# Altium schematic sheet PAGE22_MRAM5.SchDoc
size 381 x 381 mm; SheetNumber: 23; SheetTotal: 28
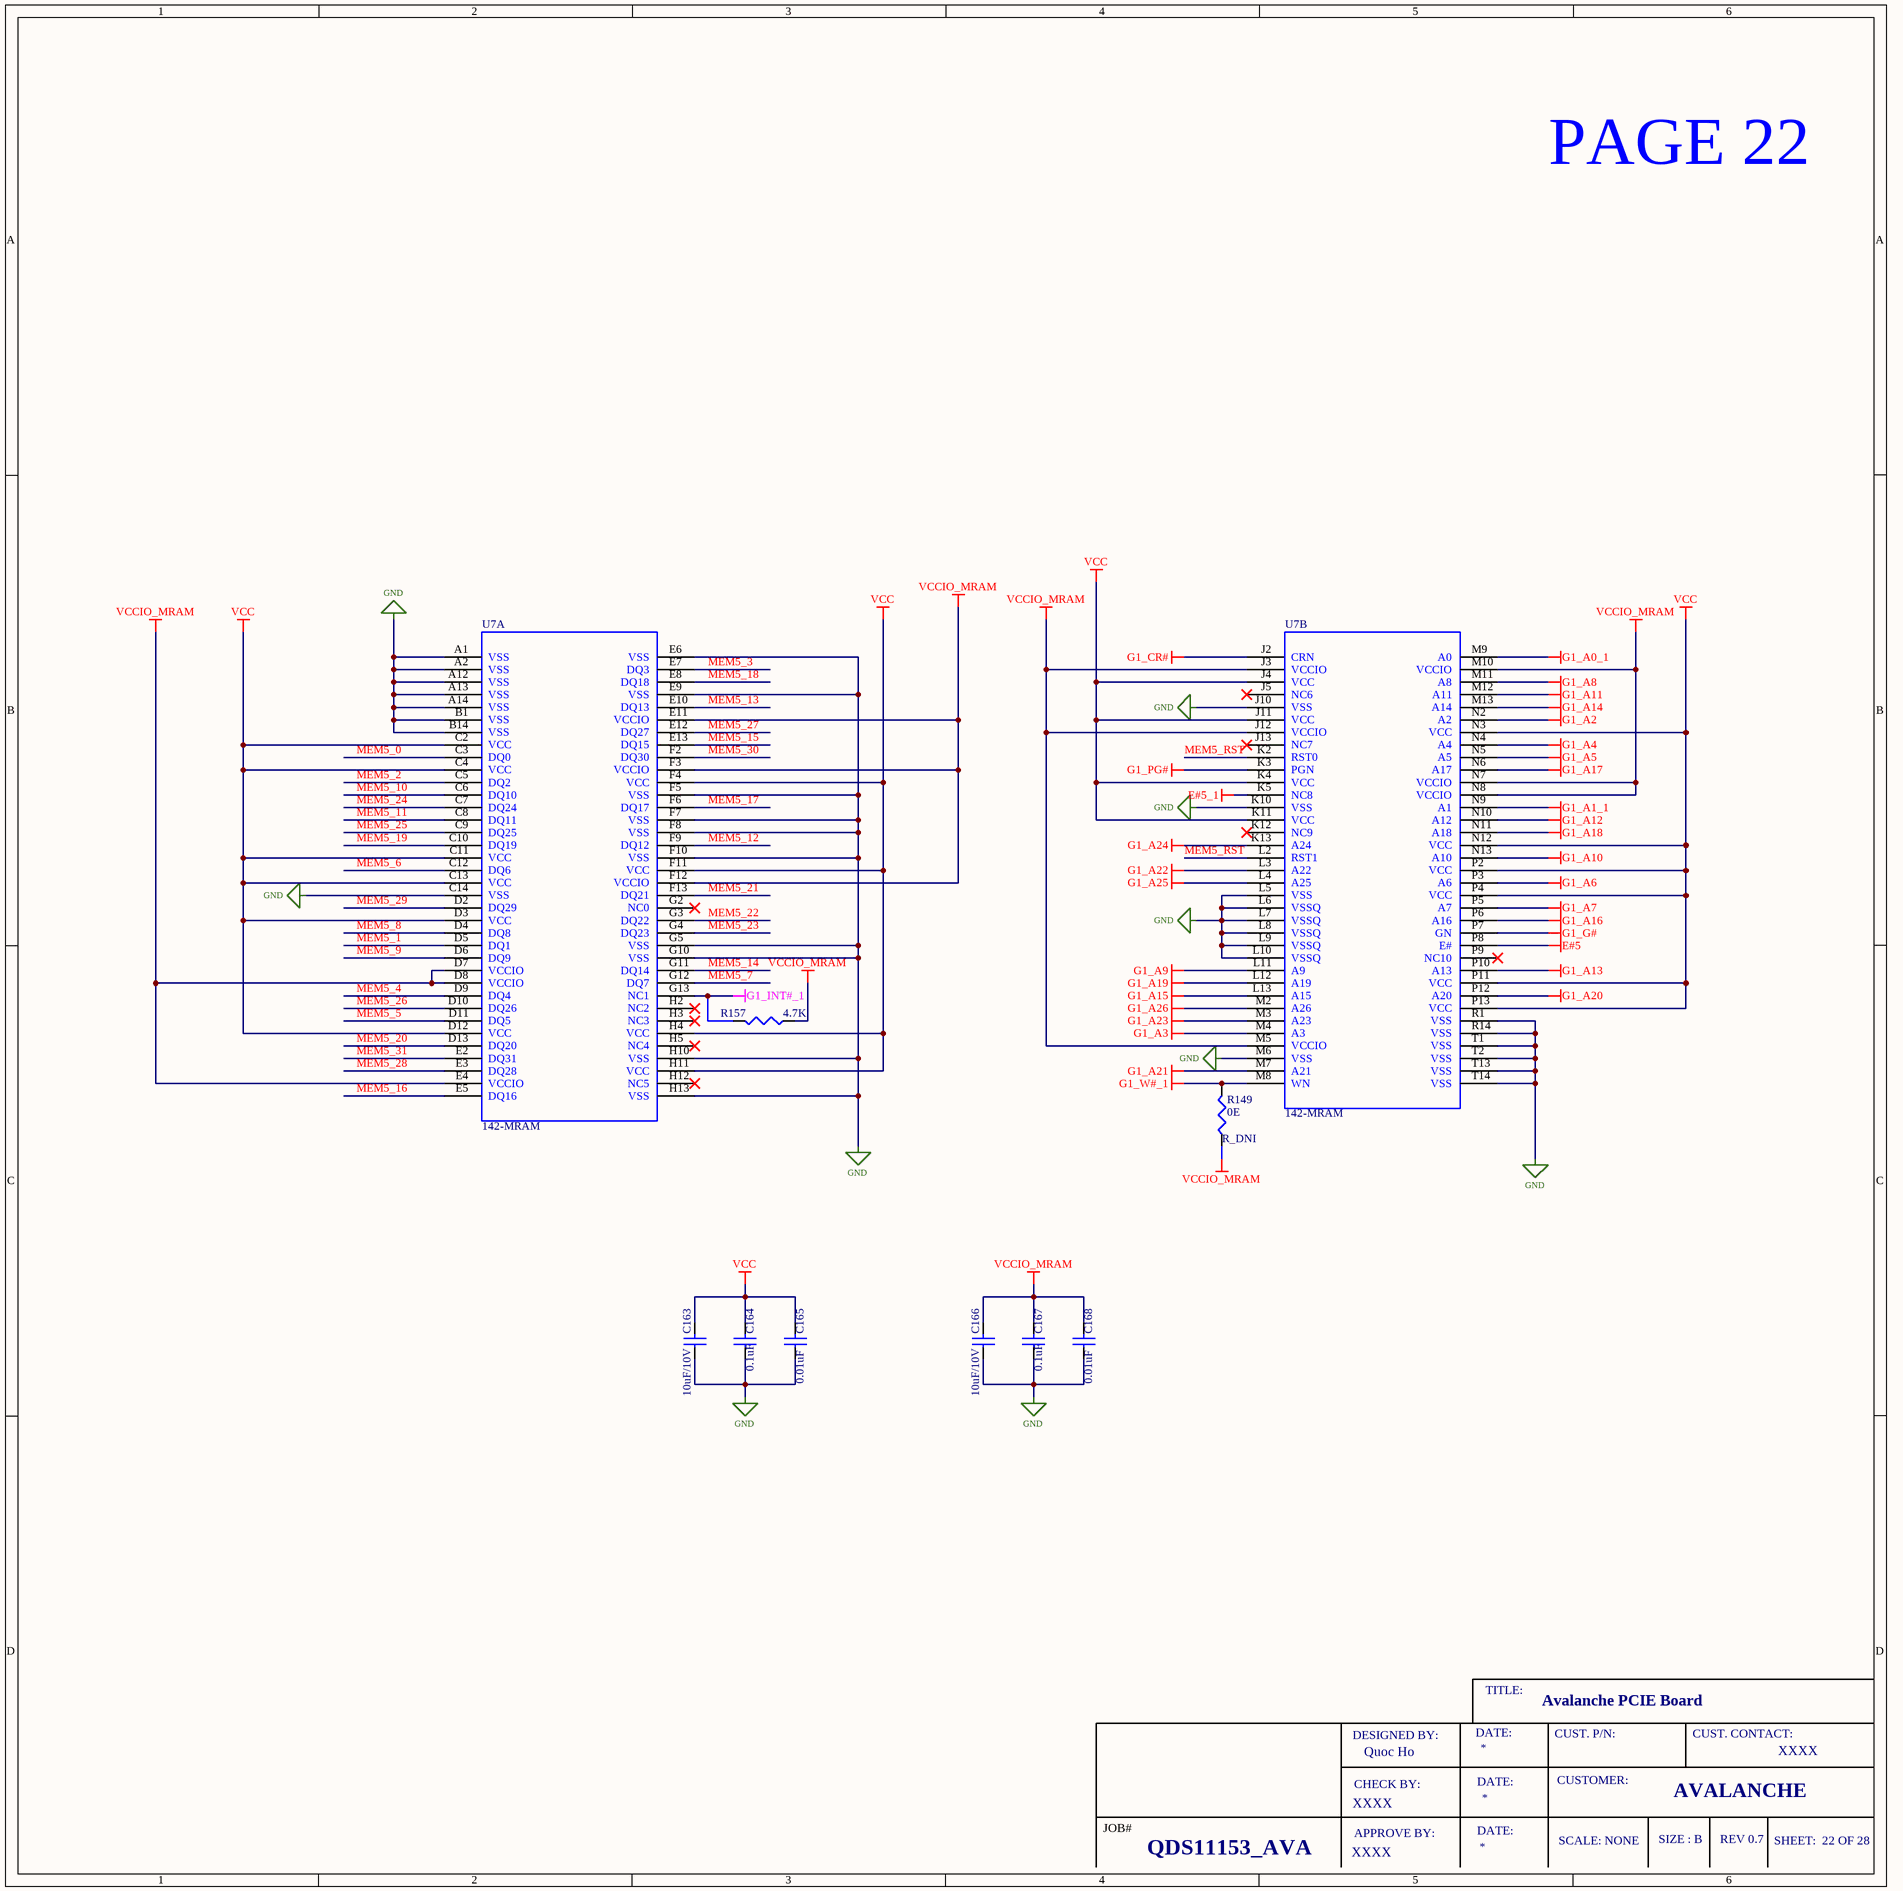
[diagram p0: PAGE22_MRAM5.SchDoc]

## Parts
C163  10uF/10V  [CN_0402]
C164  0.1uF  [CN_0402]
C165  0.01uF  [CN_0402]
C166  10uF/10V  [CN_0402]
C167  0.1uF  [CN_0402]
C168  0.01uF  [CN_0402]
R149  0E  [RN_0402]
R157  4.7K  [RN_0402]
U7  142-MRAM  [142-MRAM]  (parts A,B of 2)

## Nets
E#5: U7.P8(E#)
E#5_1: U7.K5(NC8)
G1_A0_1: U7.M9(A0)
G1_A1_1: U7.N9(A1)
G1_A2: U7.N2(A2)
G1_A3: U7.M4(A3)
G1_A4: U7.N4(A4)
G1_A5: U7.N5(A5)
G1_A6: U7.P3(A6)
G1_A7: U7.P5(A7)
G1_A8: U7.M11(A8)
G1_A9: U7.L11(A9)
G1_A10: U7.N13(A10)
G1_A11: U7.M12(A11)
G1_A12: U7.N10(A12)
G1_A13: U7.P10(A13)
G1_A14: U7.M13(A14)
G1_A15: U7.L13(A15)
G1_A16: U7.P6(A16)
G1_A17: U7.N6(A17)
G1_A18: U7.N11(A18)
G1_A19: U7.L12(A19)
G1_A20: U7.P12(A20)
G1_A21: U7.M7(A21)
G1_A22: U7.L3(A22)
G1_A23: U7.M3(A23)
G1_A24: U7.K13(A24)
G1_A25: U7.L4(A25)
G1_A26: U7.M2(A26)
G1_CR#: U7.J2(CRN)
G1_G#: U7.P7(GN)
G1_INT#_1: R157.2 U7.G13(NC1)
G1_PG#: U7.K3(PGN)
G1_W#_1: R149.2 U7.M8(WN)
GND: C163.1 C164.1 C165.1 C166.1 C167.1 C168.1 U7.A1(VSS) U7.A2(VSS) U7.A12(VSS) U7.A13(VSS) U7.A14(VSS) U7.B1(VSS) U7.B14(VSS) U7.C14(VSS) U7.E6(VSS) U7.E9(VSS) U7.F5(VSS) U7.F7(VSS) U7.F8(VSS) U7.F10(VSS) U7.G5(VSS) U7.G10(VSS) U7.H10(VSS) U7.H13(VSS) U7.J10(VSS) U7.K10(VSS) U7.L5(VSS) U7.L6(VSSQ) U7.L7(VSSQ) U7.L8(VSSQ) U7.L9(VSSQ) U7.L10(VSSQ) U7.M6(VSS) U7.R1(VSS) U7.R14(VSS) U7.T1(VSS) U7.T2(VSS) U7.T13(VSS) U7.T14(VSS)
VCC: C163.2 C164.2 C165.2 U7.C2(VCC) U7.C4(VCC) U7.C11(VCC) U7.C13(VCC) U7.D3(VCC) U7.D12(VCC) U7.F4(VCC) U7.F11(VCC) U7.H4(VCC) U7.H11(VCC) U7.J4(VCC) U7.J11(VCC) U7.K4(VCC) U7.K11(VCC) U7.N3(VCC) U7.N12(VCC) U7.P2(VCC) U7.P4(VCC) U7.P11(VCC) U7.P13(VCC)
VCCIO_MRAM: C166.2 C167.2 C168.2 R149.1 R157.1 U7.D7(VCCIO) U7.D8(VCCIO) U7.E4(VCCIO) U7.E11(VCCIO) U7.F3(VCCIO) U7.F12(VCCIO) U7.J3(VCCIO) U7.J12(VCCIO) U7.M5(VCCIO) U7.M10(VCCIO) U7.N7(VCCIO) U7.N8(VCCIO)
MEM5_0: U7.C3(DQ0)
MEM5_1: U7.D5(DQ1)
MEM5_2: U7.C5(DQ2)
MEM5_3: U7.E7(DQ3)
MEM5_4: U7.D9(DQ4)
MEM5_5: U7.D11(DQ5)
MEM5_6: U7.C12(DQ6)
MEM5_7: U7.G12(DQ7)
MEM5_8: U7.D4(DQ8)
MEM5_9: U7.D6(DQ9)
MEM5_10: U7.C6(DQ10)
MEM5_11: U7.C8(DQ11)
MEM5_12: U7.F9(DQ12)
MEM5_13: U7.E10(DQ13)
MEM5_14: U7.G11(DQ14)
MEM5_15: U7.E13(DQ15)
MEM5_16: U7.E5(DQ16)
MEM5_17: U7.F6(DQ17)
MEM5_18: U7.E8(DQ18)
MEM5_19: U7.C10(DQ19)
MEM5_20: U7.D13(DQ20)
MEM5_21: U7.F13(DQ21)
MEM5_22: U7.G3(DQ22)
MEM5_23: U7.G4(DQ23)
MEM5_24: U7.C7(DQ24)
MEM5_25: U7.C9(DQ25)
MEM5_26: U7.D10(DQ26)
MEM5_27: U7.E12(DQ27)
MEM5_28: U7.E3(DQ28)
MEM5_29: U7.D2(DQ29)
MEM5_30: U7.F2(DQ30)
MEM5_31: U7.E2(DQ31)
MEM5_RST: U7.K2(RST0) U7.L2(RST1)

Not connected (* = marked no-connect by the designer): U7 G2(NC0)* H2(NC2)* H3(NC3)* H5(NC4)* H12(NC5)* J5(NC6)* J13(NC7)* K12(NC9)* P9(NC10)*

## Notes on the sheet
- PAGE 22
- TITLE:
- Avalanche PCIE Board
- DESIGNED BY:
- CHECK BY:
- Quoc Ho
- DATE:
- CUST. P/N:
- CUSTOMER:
- CUST. CONTACT:
- XXXX
- JOB#
- APPROVE BY:
- SCALE: NONE
- SIZE : B
- AVALANCHE
- REV 0.7
- SHEET:  22 OF 28
- QDS11153_AVA

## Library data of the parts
C163 = CAP: CAP CER 10UF 10V X5R 0402; Manufacturer Part Number: GRM155R61A106ME11D; Manufacturer: Murata Electronics
C164 C167 = CAP: CAP CER 0.1UF 50V X7R 0402; Manufacturer: Murata Electronics; Manufacturer Part Number: GCM155R71H104KE02J
C165 C168 = CAP: 0.01 µF, 25 V, 0402 [1005 Metric], ± 10%, X7R; Manufacturer Part Number: CC0402JRX7R8BB103; Manufacturer: YAGEO
C166 = CAP: CAP CER 10UF 10V X5R 0402; Manufacturer: Murata Electronics; Manufacturer Part Number: GRM155R61A106ME11D
R149 = RES: RES 0 OHM JUMPER 1/16W 0402; Manufacturer: YAGEO; Manufacturer Part Number: RC0402FR-070RL
R157 = RES: RES 4.7K OHM 1% 1/16W 0402; Manufacturer Part Number: RC0402FR-134K7L; Manufacturer: YAGEO
U7 = 142-MRAM: IC 142-MRAM MEMORY; Manufacturer: Avalanche Technology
